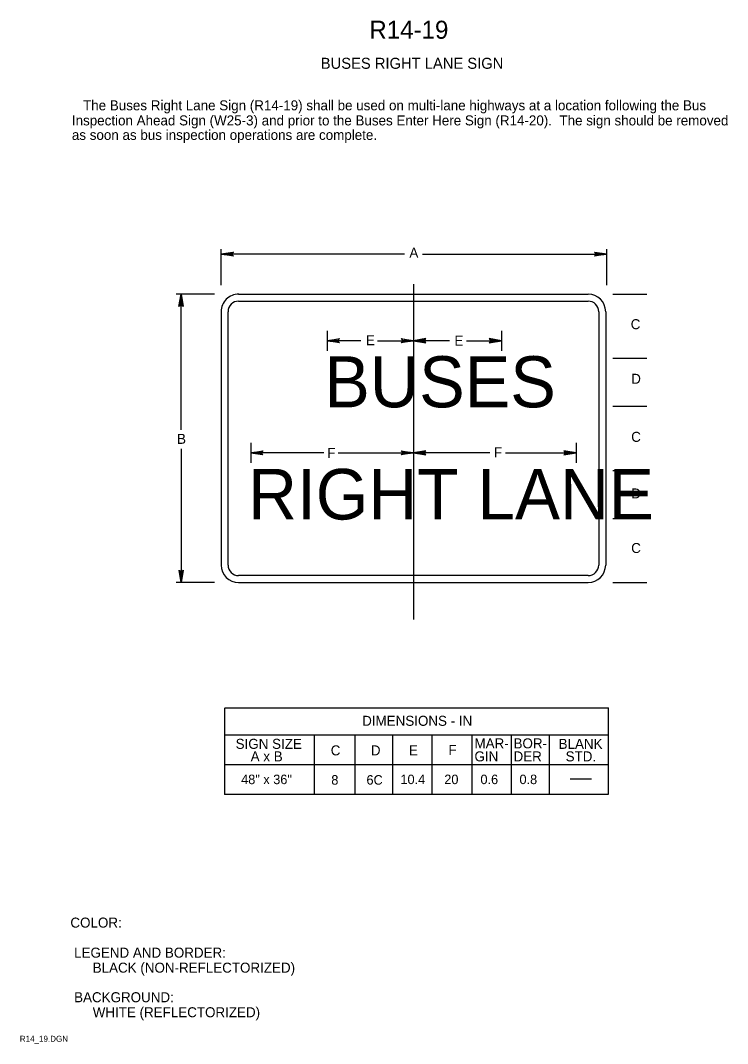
# Model space of a CAD drawing. Extents: x 0.013 to 0.189, y 0.004 to 0.259.
import ezdxf

# ---------------------------------------------------------------- set-up
doc = ezdxf.new("R2010")
doc.units = 0
for name, color, linetype in [('1', 7, 'Continuous'), ('11', 7, 'Continuous'), ('12', 7, 'Continuous'), ('3', 7, 'Continuous')]:
    doc.layers.add(name, color=color, linetype=linetype)

# ---------------------------------------------------------------- blocks, each defined once
blk = doc.blocks.new('RARROW')
at = {"layer": '3'}
for p, q in [((-2.156, 0.285), (-2.2665, 0.384625)), ((-2.2665, 0.384625), (0, 0)), ((0, 0), (-2.2665, -0.379125)), ((-2.156, 0.285), (-2.075625, 0.12075)), ((0, 0), (-2.156, 0.285)), ((-2.14975, -0.2705), (0, 0)), ((-2.075625, 0.12075), (0, 0)), ((0, 0), (-2.074, -0.108)), ((-2.2665, -0.379125), (-2.14975, -0.2705)), ((-2.074, -0.108), (-2.14975, -0.2705))]:
    blk.add_line(p, q, dxfattribs=at)

msp = doc.modelspace()

# ---------------------------------------------------------------- linework, layer by layer
at = {"layer": '11'}
for p, q in [((0.06713, 0.191), (0.15437, 0.191)), ((0.06275, 0.18662), (0.06275, 0.12337)), ((0.15875, 0.18662), (0.15875, 0.12337)), ((0.06713, 0.119), (0.15437, 0.119))]:
    msp.add_line(p, q, dxfattribs=at)
for centre, radius, start, end in [((0.06714, 0.18661), 0.00439, 89.8372, 179.8372), ((0.15437, 0.18662), 0.00438, 0, 90), ((0.06713, 0.12337), 0.00438, 180, 270), ((0.15437, 0.12337), 0.00438, 270, 0)]:
    msp.add_arc(centre, radius, start, end, dxfattribs=at)
at = {"layer": '3'}
for p, q in [((0.06275, 0.19325), (0.06275, 0.20225)), ((0.159, 0.19325), (0.159, 0.20225)), ((0.1085, 0.201), (0.06275, 0.201)), ((0.113, 0.201), (0.159, 0.201)), ((0.11075, 0.1935), (0.11075, 0.10975)), ((0.06112, 0.191), (0.0515, 0.191)), ((0.05275, 0.15713), (0.05275, 0.191)), ((0.06713, 0.18925), (0.15437, 0.18925)), ((0.1605, 0.191), (0.169, 0.191)), ((0.0645, 0.12337), (0.0645, 0.18662)), ((0.157, 0.18662), (0.157, 0.12337)), ((0.08925, 0.18188), (0.08925, 0.17688)), ((0.13275, 0.18188), (0.13275, 0.17688)), ((0.09763, 0.17938), (0.08925, 0.17938)), ((0.10175, 0.17938), (0.11075, 0.17938)), ((0.11975, 0.17938), (0.11075, 0.17938)), ((0.124, 0.17938), (0.13275, 0.17938)), ((0.1605, 0.175), (0.169, 0.175)), ((0.1605, 0.163), (0.169, 0.163)), ((0.07013, 0.15388), (0.07013, 0.14888)), ((0.15138, 0.15388), (0.15138, 0.14888)), ((0.05275, 0.15238), (0.05275, 0.119)), ((0.08837, 0.15138), (0.07013, 0.15138)), ((0.092, 0.15138), (0.11075, 0.15138)), ((0.12987, 0.15138), (0.11075, 0.15138)), ((0.13375, 0.15138), (0.15138, 0.15138)), ((0.1605, 0.147), (0.169, 0.147)), ((0.1605, 0.135), (0.169, 0.135)), ((0.15437, 0.12075), (0.06713, 0.12075)), ((0.06112, 0.119), (0.0515, 0.119)), ((0.1605, 0.119), (0.169, 0.119)), ((0.06363, 0.08775), (0.06363, 0.06613)), ((0.06375, 0.08771), (0.15945, 0.08771)), ((0.15938, 0.08775), (0.15938, 0.06613)), ((0.15938, 0.08088), (0.06363, 0.08088)), ((0.086, 0.08083), (0.086, 0.06608)), ((0.09613, 0.08088), (0.09613, 0.06613)), ((0.1055, 0.08088), (0.1055, 0.06613)), ((0.11538, 0.08088), (0.11538, 0.06613)), ((0.12537, 0.08083), (0.12537, 0.06608)), ((0.13512, 0.08083), (0.13512, 0.06608)), ((0.14463, 0.08088), (0.14463, 0.06613)), ((0.15938, 0.0735), (0.06363, 0.0735)), ((0.14986, 0.07004), (0.15517, 0.07004)), ((0.15938, 0.06613), (0.06363, 0.06613))]:
    msp.add_line(p, q, dxfattribs=at)
for centre, start, end in [((0.06713, 0.18662), 90, 180), ((0.15437, 0.18662), 0, 90), ((0.06713, 0.12337), 180, 270), ((0.15437, 0.12337), 270, 0)]:
    msp.add_arc(centre, 0.00263, start, end, dxfattribs=at)

# ---------------------------------------------------------------- block references
at = {"layer": '3', "xscale": 0.0013566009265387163}
for p, yscale, rotation in [((0.06275, 0.201), 0.0013419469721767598, 180), ((0.05275, 0.191), 0.0013419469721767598, 90), ((0.08925, 0.17938), 0.0013419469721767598, 180), ((0.11075, 0.17938), -0.0013419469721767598, 180), ((0.07013, 0.15138), 0.0013419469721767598, 180), ((0.11075, 0.15138), -0.0013419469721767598, 180), ((0.05275, 0.119), 0.0013419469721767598, -90)]:
    msp.add_blockref('RARROW', p, dxfattribs=dict(at, yscale=yscale, rotation=rotation))
for p, yscale in [((0.159, 0.201), 0.0013419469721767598), ((0.11075, 0.17938), 0.0013419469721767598), ((0.13275, 0.17938), -0.0013419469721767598), ((0.11075, 0.15138), 0.0013419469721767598), ((0.15138, 0.15138), -0.0013419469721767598)]:
    msp.add_blockref('RARROW', p, dxfattribs=dict(at, yscale=yscale))

# ---------------------------------------------------------------- texts
at = {"layer": '1'}
for s, height, p in [('R14-19', 0.0045, (0.09975, 0.25475)), ('BUSES RIGHT LANE SIGN', 0.0027503, (0.08763, 0.24725)), ('   The Buses Right Lane Sign (R14-19) shall be used on multi-lane highways at a location following the Bus', 0.00249975, (0.0255, 0.23688)), ('Inspection Ahead Sign (W25-3) and prior to the Buses Enter Here Sign (R14-20).  The sign should be removed', 0.00249975, (0.0255, 0.23312)), ('as soon as bus inspection operations are complete.', 0.0024998, (0.0255, 0.2295)), ('COLOR:', 0.0025, (0.02513, 0.03288)), (' LEGEND AND BORDER:', 0.0024998, (0.02513, 0.02538)), ('      BLACK (NON-REFLECTORIZED)', 0.0024998, (0.02513, 0.02163)), (' BACKGROUND:', 0.0024998, (0.02513, 0.01425)), ('      WHITE (REFLECTORIZED)', 0.0024998, (0.02513, 0.0105)), ('R14_19.DGN', 0.0015, (0.0125, 0.00438))]:
    msp.add_text(s, height=height, dxfattribs=at).set_placement(p)
at = {"layer": '12'}
for s, height, p in [('BUSES', 0.01275, (0.0885, 0.16275)), ('RIGHT LANE', 0.012625, (0.0695, 0.13475))]:
    msp.add_text(s, height=height, dxfattribs=at).set_placement(p)
at = {"layer": '3'}
for s, height, p in [('A', 0.0025, (0.10975, 0.20012)), ('C', 0.0025, (0.165, 0.18225)), ('E', 0.0025, (0.09888, 0.17825)), ('E', 0.0025, (0.121, 0.17813)), ('D', 0.0025, (0.16512, 0.16862)), ('B', 0.0025, (0.05175, 0.15363)), ('C', 0.0025, (0.16512, 0.15413)), ('F', 0.0025, (0.08925, 0.15013)), ('F', 0.0025, (0.13087, 0.15025)), ('D', 0.0025, (0.16512, 0.14)), ('C', 0.0025, (0.16512, 0.12638)), ('DIMENSIONS - IN', 0.0024998, (0.09796, 0.08325)), ('SIGN SIZE', 0.0025, (0.06638, 0.0775)), ('MAR-', 0.0025, (0.126, 0.07762)), ('BOR-', 0.0025, (0.13575, 0.07762)), ('BLANK', 0.0025, (0.147, 0.0775)), ('A x B', 0.0025, (0.07013, 0.07437)), ('C', 0.0025, (0.09012, 0.07587)), ('D', 0.0025, (0.10013, 0.07587)), ('E', 0.0025, (0.10963, 0.07587)), ('F', 0.0025, (0.1195, 0.076)), ('GIN', 0.0025, (0.126, 0.07437)), ('DER', 0.0025, (0.13575, 0.07437)), ('STD.', 0.0025, (0.14875, 0.07437)), ('48" x 36"', 0.002375, (0.06775, 0.06869)), ('8', 0.00238, (0.09026, 0.06856)), ('6C', 0.002375, (0.09904, 0.06856)), ('10.4', 0.002375, (0.10751, 0.06869)), ('20', 0.002375, (0.11846, 0.06869)), ('0.6', 0.002375, (0.12749, 0.06869)), ('0.8', 0.002375, (0.13723, 0.06869))]:
    msp.add_text(s, height=height, dxfattribs=at).set_placement(p)

doc.saveas('drawing.dxf')
